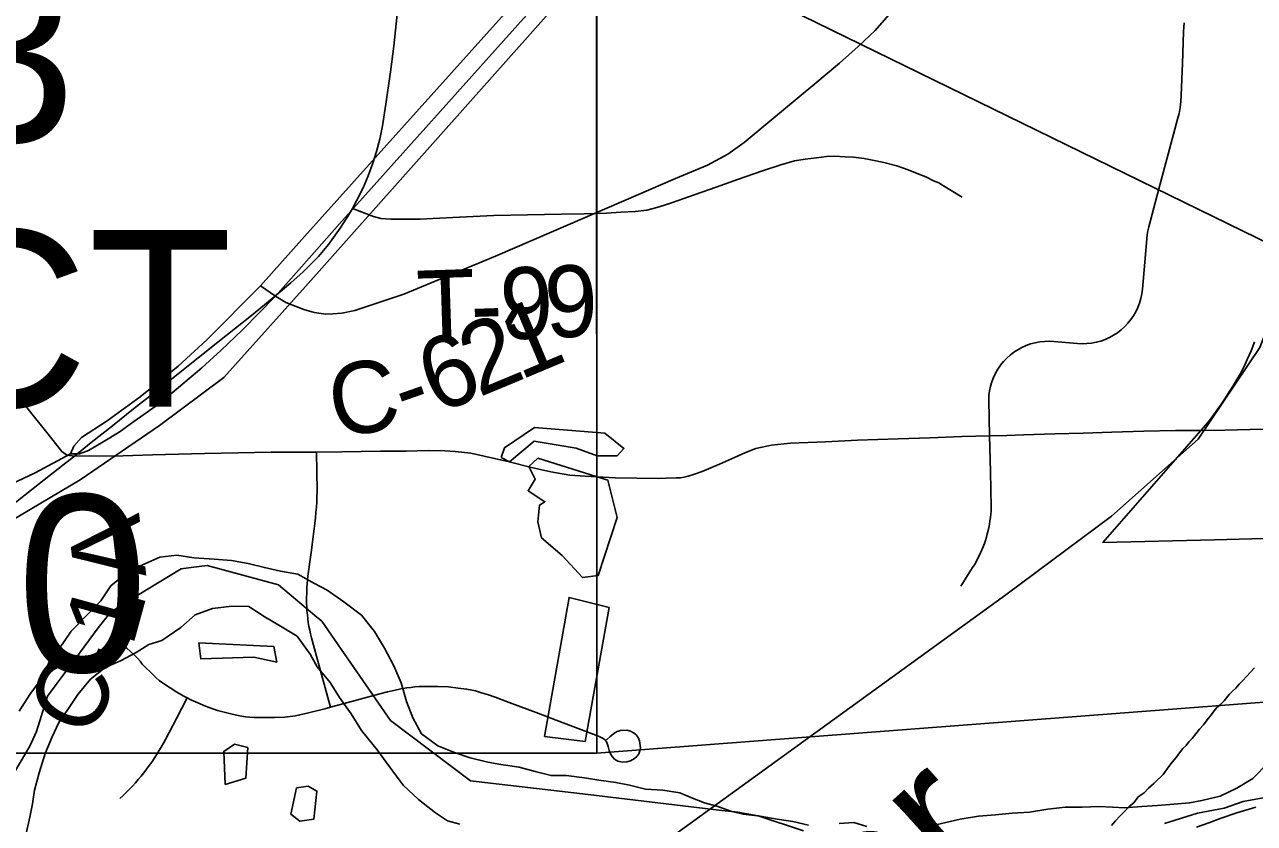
# Model space of a CAD drawing. Extents: x -6.1 to 38, y -7.7 to 22.
# Drawn here: x 4.995 to 5.97, y 18.594 to 19.227 of the extents above; entities that cross this region are included whole.
import ezdxf

# ---------------------------------------------------------------- set-up
doc = ezdxf.new("R2010")
doc.units = 0
for name, color, linetype in [('GM_X_Corporation', 7, 'Continuous'), ('GM_X_County_Road', 7, 'Continuous'), ('GM_X_County_Road_Text', 7, 'Continuous'), ('GM_X_Major_River', 7, 'Continuous'), ('GM_X_Major_River_Text', 7, 'Continuous'), ('GM_X_Minor_Lake', 7, 'Continuous'), ('GM_X_Minor_River', 7, 'Continuous'), ('GM_X_Rail_Line', 7, 'Continuous'), ('GM_X_Township_Road', 7, 'Continuous'), ('GM_X_Township_Road_Text', 7, 'Continuous'), ('GM_X_US_Route', 7, 'Continuous'), ('SH_Text', 7, 'Continuous')]:
    doc.layers.add(name, color=color, linetype=linetype)

msp = doc.modelspace()

# ---------------------------------------------------------------- linework, layer by layer
at = {"layer": 'GM_X_Corporation'}
for points in [[(5.9704, 18.97578), (5.96908, 18.97223), (5.9677, 18.9687), (5.96623, 18.9652), (5.96471, 18.96171), (5.96191, 18.95576), (5.95921, 18.9508), (5.95636, 18.94587), (5.95342, 18.941), (5.95044, 18.93618), (5.94735, 18.93141), (5.94418, 18.9267), (5.94091, 18.92204), (5.93469, 18.9136), (5.92962, 18.90779), (5.85031, 18.81673), (5.93858, 18.81896), (5.97794, 18.81995)], [(4.98437, 18.62941), (4.9995, 18.65526), (5.0049, 18.66688), (5.01365, 18.69493), (5.02803, 18.71436), (5.03887, 18.72902), (5.05368, 18.74904), (5.06379, 18.76178), (5.06483, 18.76241), (5.07927, 18.77124), (5.0921, 18.77908), (5.11964, 18.79595), (5.12546, 18.79667), (5.14011, 18.79852), (5.19671, 18.7833), (5.22703, 18.75764), (5.22783, 18.75696), (5.23099, 18.75429), (5.25639, 18.71764), (5.28554, 18.67556), (5.34884, 18.62786), (5.44222, 18.61682), (5.54829, 18.60429), (5.54852, 18.60426), (5.56082, 18.60302), (5.577, 18.60014), (5.61302, 18.58812)], [(5.89915, 18.59391), (5.92512, 18.60216), (5.94641, 18.60603), (5.96153, 18.61146), (5.98899, 18.6163)]]:
    msp.add_lwpolyline(points, dxfattribs=at)
at = {"layer": 'GM_X_County_Road'}
for points in [[(4.98326, 18.84453), (5.00739, 18.86365), (5.02582, 18.87809), (5.03494, 18.88525), (5.04812, 18.896), (5.06502, 18.90931), (5.08191, 18.92262), (5.09959, 18.9366), (5.11726, 18.95058), (5.13296, 18.96312), (5.14867, 18.97565), (5.16264, 18.98668), (5.17662, 18.99771), (5.19163, 19.01014), (5.20663, 19.02256), (5.21641, 19.03139), (5.22844, 19.04363), (5.23637, 19.05312), (5.24549, 19.06585), (5.25143, 19.07497), (5.25534, 19.08164), (5.25861, 19.08753), (5.26377, 19.09803), (5.26771, 19.10748), (5.27144, 19.11759), (5.27439, 19.12665), (5.277, 19.1365), (5.27917, 19.147), (5.28194, 19.16423), (5.28539, 19.18996), (5.28811, 19.21035), (5.2914, 19.24076)], [(5.18251, 19.02026), (5.19424, 19.01215), (5.20249, 19.00709), (5.21681, 19.00141), (5.22495, 18.99919), (5.23432, 18.99771), (5.23975, 18.99795), (5.24691, 18.99845), (5.25728, 19.00067), (5.29602, 19.01375), (5.36881, 19.04385), (5.47048, 19.08778), (5.51144, 19.1053), (5.53686, 19.11591), (5.5529, 19.12455), (5.56598, 19.13392), (5.58473, 19.14947), (5.62199, 19.18031), (5.64149, 19.19685), (5.65629, 19.20993), (5.66962, 19.22276), (5.68788, 19.24349)]]:
    msp.add_lwpolyline(points, dxfattribs=at)
at = {"layer": 'GM_X_Major_River'}
for points in [[(5.61689, 18.59268), (5.60439, 18.59564), (5.5919, 18.59745), (5.57865, 18.59964), (5.56502, 18.60144), (5.55518, 18.60365), (5.54418, 18.60775), (5.53433, 18.61034), (5.52485, 18.61407), (5.51499, 18.61817), (5.50136, 18.62036), (5.48774, 18.62103), (5.47486, 18.62435), (5.46425, 18.62656), (5.45063, 18.62836), (5.43927, 18.63018), (5.42489, 18.63199), (5.41279, 18.63191), (5.40028, 18.63524), (5.3874, 18.63856), (5.37302, 18.64074), (5.36279, 18.64257), (5.34878, 18.64589), (5.33627, 18.65036), (5.323, 18.65558), (5.31007, 18.66497), (5.30318, 18.67782), (5.29818, 18.69068), (5.29392, 18.70544), (5.28816, 18.71905), (5.28088, 18.73303), (5.27286, 18.74625), (5.26256, 18.75908), (5.2485, 18.7696), (5.2352, 18.77899), (5.22533, 18.78424), (5.21204, 18.79174), (5.19841, 18.79392), (5.18554, 18.79687), (5.17266, 18.8002), (5.1594, 18.80238), (5.14578, 18.80343), (5.12951, 18.80446), (5.11626, 18.80665), (5.10266, 18.80504), (5.08832, 18.79888), (5.07551, 18.79197), (5.06385, 18.78241), (5.05599, 18.7706), (5.03232, 18.74656), (5.0252, 18.73589), (5.01583, 18.72369), (5.00911, 18.70924), (4.99974, 18.69628), (4.99113, 18.68296)], [(4.99669, 18.58592), (4.99963, 18.59883), (5.00183, 18.60946), (5.00327, 18.62047), (5.00696, 18.63414), (5.01178, 18.64934), (5.01736, 18.66265), (5.02258, 18.67406), (5.0297, 18.68435), (5.03757, 18.69616), (5.0477, 18.70836), (5.05936, 18.71753), (5.07143, 18.72292), (5.08386, 18.72946), (5.09403, 18.73597), (5.10422, 18.73907), (5.11929, 18.74941), (5.13057, 18.75934), (5.14453, 18.76436), (5.15964, 18.76636), (5.17326, 18.76607), (5.18541, 18.75819), (5.19832, 18.75031), (5.21161, 18.74243), (5.22192, 18.7281), (5.22728, 18.71827), (5.23757, 18.70583), (5.24521, 18.69374)], [(5.85692, 18.59224), (5.86026, 18.5961), (5.86399, 18.59997), (5.86735, 18.60346), (5.87108, 18.60733), (5.87482, 18.61044), (5.87815, 18.61506), (5.88304, 18.61819), (5.88638, 18.62205), (5.8905, 18.62555), (5.89348, 18.62865), (5.8961, 18.63097), (5.89796, 18.63291), (5.90056, 18.63638), (5.90241, 18.63907), (5.90501, 18.64254), (5.90836, 18.6464), (5.91095, 18.64987), (5.91355, 18.65334), (5.91616, 18.65567), (5.91839, 18.65876), (5.921, 18.66146), (5.92397, 18.66494), (5.92694, 18.66879), (5.92992, 18.67227), (5.93289, 18.67613), (5.93623, 18.68037), (5.93994, 18.68538), (5.94368, 18.68849), (5.94629, 18.6912), (5.94815, 18.69352), (5.95038, 18.69622), (5.95299, 18.69893), (5.95561, 18.70126), (5.95821, 18.70434), (5.96119, 18.70744), (5.96417, 18.71054), (5.96715, 18.71401), (5.97051, 18.71749)], [(5.24521, 18.69374), (5.25437, 18.68091), (5.2624, 18.66769), (5.27499, 18.65223), (5.28491, 18.63864), (5.29559, 18.6243), (5.30777, 18.61301), (5.32108, 18.60248), (5.33057, 18.5961), (5.34042, 18.5935)], [(5.98116, 18.64212), (5.96914, 18.62952), (5.95633, 18.62185), (5.94313, 18.6157)], [(5.94313, 18.6157), (5.92878, 18.61219), (5.91896, 18.61023), (5.90649, 18.60939), (5.89364, 18.60817), (5.88116, 18.60733), (5.86755, 18.60648), (5.85772, 18.60679), (5.84712, 18.60748), (5.83389, 18.60702), (5.82027, 18.60692), (5.80667, 18.60532), (5.79193, 18.60294), (5.77832, 18.6021), (5.7651, 18.60087), (5.75149, 18.59964), (5.73713, 18.59727), (5.70994, 18.59103)], [(5.92438, 18.59093), (5.9342, 18.59441), (5.944, 18.59827), (5.95646, 18.60252), (5.97155, 18.60679)], [(5.66304, 18.59147), (5.65281, 18.59482), (5.64109, 18.59398)]]:
    msp.add_lwpolyline(points, dxfattribs=at)
at = {"layer": 'GM_X_Minor_Lake'}
for points in [[(5.46524, 18.88559), (5.47051, 18.8913), (5.45532, 18.90341), (5.39967, 18.90783), (5.37589, 18.89183), (5.37328, 18.88423)], [(5.37328, 18.88423), (5.37972, 18.88083), (5.39933, 18.8972), (5.43266, 18.89158), (5.44934, 18.88555), (5.46524, 18.88559)], [(5.40242, 18.88354), (5.39526, 18.87707), (5.40022, 18.86683), (5.39458, 18.85771), (5.40787, 18.84901), (5.40372, 18.84635), (5.40226, 18.83306), (5.40534, 18.82054), (5.42168, 18.80653)], [(5.42168, 18.80653), (5.43765, 18.78911), (5.45013, 18.79066), (5.46507, 18.83663), (5.45775, 18.86621), (5.40242, 18.88354)], [(5.45895, 18.76525), (5.42712, 18.77315), (5.40754, 18.66303)], [(5.40754, 18.66303), (5.43973, 18.65893), (5.45895, 18.76525)], [(5.13359, 18.73714), (5.13516, 18.72462), (5.17716, 18.72586), (5.19535, 18.72173)], [(5.19535, 18.72173), (5.19302, 18.73425), (5.13359, 18.73714)], [(5.17255, 18.65411), (5.16194, 18.65674), (5.15327, 18.65103), (5.15451, 18.62484)], [(5.15451, 18.62484), (5.17077, 18.62981), (5.17255, 18.65411)], [(5.21092, 18.62232), (5.20647, 18.60143), (5.21368, 18.59575), (5.22465, 18.5973)], [(5.22465, 18.5973), (5.2272, 18.6197), (5.22037, 18.62348), (5.21092, 18.62232)]]:
    msp.add_lwpolyline(points, dxfattribs=at)
at = {"layer": 'GM_X_Minor_River'}
msp.add_lwpolyline([(4.8608, 18.77196), (4.98429, 18.83357), (5.03941, 18.86634), (5.10243, 18.90938), (5.15337, 18.94745), (5.21821, 19.01967), (5.96039, 19.85374)], dxfattribs=at)
at = {"layer": 'GM_X_Rail_Line'}
msp.add_lwpolyline([(4.164, 17.08105), (4.22288, 17.11422), (4.28514, 17.16362), (4.3773, 17.2385), (4.46626, 17.31066), (4.52352, 17.37506), (4.57967, 17.45347), (4.643, 17.54537), (5.03778, 18.11028), (5.18813, 18.32179), (5.2285, 18.37664), (5.2671, 18.40903), (5.31379, 18.44323), (5.44065, 18.5342), (5.77322, 18.77518), (5.85708, 18.83753), (5.92575, 18.89871), (5.97472, 18.97128), (6.00159, 19.04095), (6.01392, 19.09362), (6.04108, 19.2873)], dxfattribs=at)
at = {"layer": 'GM_X_Township_Road'}
for points in [[(5.76043, 18.90123), (5.75969, 18.92961), (5.75988, 18.93332), (5.76036, 18.937), (5.76112, 18.94062), (5.76221, 18.94419), (5.76354, 18.94764), (5.7651, 18.951), (5.76695, 18.95421), (5.76909, 18.95728), (5.77141, 18.96015), (5.77397, 18.96285), (5.77672, 18.96533), (5.77966, 18.9676), (5.78274, 18.96962), (5.78601, 18.97141), (5.78942, 18.97292), (5.79288, 18.97416), (5.79648, 18.97513), (5.80013, 18.97582), (5.80383, 18.97622), (5.80752, 18.97633), (5.81122, 18.97615), (5.83012, 18.97448), (5.83382, 18.9743), (5.83756, 18.9744), (5.84126, 18.9748), (5.84491, 18.9755), (5.84851, 18.97647), (5.85201, 18.97772), (5.85538, 18.97925), (5.85865, 18.98104), (5.86178, 18.98307), (5.86471, 18.98535), (5.86747, 18.98785), (5.87003, 18.99056), (5.87235, 18.99346), (5.87443, 18.99652), (5.87628, 18.99976), (5.8779, 19.00312), (5.87922, 19.00659), (5.88027, 19.01017), (5.88103, 19.0138), (5.8815, 19.0175), (5.88341, 19.03908), (5.88532, 19.06067), (5.88584, 19.06394), (5.8866, 19.06716), (5.89466, 19.09716), (5.90207, 19.12472), (5.90948, 19.15227), (5.91062, 19.15697), (5.91148, 19.16174), (5.91204, 19.16653), (5.91238, 19.17136), (5.91327, 19.19646), (5.91416, 19.22155), (5.9144, 19.22527), (5.91473, 19.22867)], [(5.25534, 19.08164), (5.27194, 19.07512), (5.27787, 19.07376), (5.28583, 19.07304), (5.30904, 19.07317), (5.33486, 19.07447), (5.35113, 19.07525), (5.36739, 19.07604), (5.39419, 19.0765), (5.42099, 19.07695), (5.43891, 19.07747), (5.45685, 19.078), (5.46799, 19.07858), (5.47953, 19.07917), (5.4886, 19.08028), (5.49675, 19.08243), (5.50281, 19.08419), (5.50907, 19.0864), (5.527, 19.0926), (5.54378, 19.09861), (5.56055, 19.10461), (5.58049, 19.11136), (5.595, 19.11627), (5.60583, 19.1194), (5.61417, 19.12063), (5.62311, 19.12181), (5.63119, 19.12272), (5.63719, 19.12304), (5.64592, 19.12266), (5.65244, 19.1224), (5.66105, 19.12109), (5.6675, 19.11985), (5.6767, 19.11796), (5.68687, 19.11542), (5.69587, 19.11229), (5.70159, 19.10996), (5.70995, 19.10655), (5.71608, 19.10349), (5.72006, 19.10179), (5.72391, 19.09964), (5.7387, 19.09052)], [(4.98192, 18.94321), (5.00121, 18.91886), (5.01309, 18.90386), (5.02497, 18.88886), (5.02698, 18.8873), (5.02924, 18.88608), (5.03494, 18.88525)], [(5.9285, 18.90563), (5.94702, 18.90579), (5.96702, 18.90621), (5.98887, 18.9068), (6.0173, 18.90799), (6.03468, 18.90872), (6.05205, 18.90944), (6.06798, 18.90975), (6.08392, 18.91005), (6.10601, 18.91047), (6.12744, 18.91113), (6.15004, 18.91213), (6.16462, 18.91288), (6.18297, 18.91321), (6.20106, 18.91297), (6.22299, 18.91288), (6.24683, 18.91347), (6.26381, 18.91403), (6.28079, 18.91459), (6.31087, 18.91555), (6.33696, 18.91672), (6.35463, 18.91734), (6.37229, 18.91797)], [(5.03494, 18.88525), (5.04728, 18.88555), (5.06574, 18.88529), (5.08127, 18.88579), (5.09679, 18.88629), (5.11736, 18.88677), (5.13794, 18.88725), (5.16447, 18.88776), (5.19101, 18.88827), (5.20893, 18.88835), (5.22687, 18.88843), (5.24693, 18.88871), (5.27758, 18.88914), (5.29781, 18.88922), (5.31542, 18.88961), (5.32845, 18.88945), (5.33667, 18.88898), (5.34923, 18.88748), (5.37854, 18.88108), (5.39726, 18.87626), (5.41274, 18.87279), (5.42767, 18.87018), (5.43992, 18.86931), (5.46361, 18.86813), (5.48084, 18.86784), (5.49807, 18.86755), (5.50413, 18.86767), (5.51204, 18.86797), (5.51536, 18.86813), (5.51828, 18.8686), (5.52151, 18.86939), (5.5265, 18.87084), (5.53257, 18.8731), (5.54624, 18.87878), (5.55572, 18.88313), (5.56646, 18.88779), (5.57523, 18.89135), (5.58755, 18.8938), (5.60264, 18.89546), (5.63037, 18.89648), (5.65572, 18.89775), (5.6718, 18.8983), (5.68788, 18.89885), (5.71329, 18.89976), (5.73871, 18.90067), (5.76043, 18.90123), (5.77399, 18.90168), (5.78759, 18.90224), (5.81205, 18.90281), (5.83471, 18.90353), (5.85739, 18.90425), (5.88265, 18.90494), (5.90791, 18.90563), (5.9285, 18.90563)], [(5.73773, 18.78219), (5.74698, 18.79679), (5.74835, 18.79907), (5.74968, 18.80137), (5.75096, 18.80371), (5.75214, 18.80609), (5.75328, 18.80851), (5.75433, 18.81094), (5.75532, 18.81342), (5.75627, 18.81591), (5.75712, 18.81843), (5.75788, 18.82098), (5.7586, 18.82354), (5.75926, 18.82613), (5.75978, 18.82873), (5.76031, 18.83135), (5.76073, 18.83398), (5.76106, 18.83662), (5.76131, 18.83926), (5.76154, 18.84192), (5.76164, 18.84458), (5.76104, 18.87291), (5.76043, 18.90123)], [(5.23796, 18.68608), (5.23077, 18.71215), (5.22357, 18.73823), (5.22277, 18.74121), (5.22206, 18.7442), (5.22145, 18.74721), (5.22088, 18.75023), (5.22036, 18.75327), (5.21994, 18.75631), (5.21961, 18.75937), (5.21932, 18.76243), (5.21909, 18.7655), (5.21895, 18.76857), (5.21914, 18.78087), (5.21933, 18.78393), (5.21966, 18.787), (5.22, 18.79006), (5.2225, 18.80884), (5.225, 18.82763), (5.22552, 18.8319), (5.22599, 18.83618), (5.22642, 18.84046), (5.22675, 18.84475), (5.227, 18.84905), (5.22718, 18.85334), (5.22733, 18.85764), (5.22687, 18.88843)], [(5.063, 18.73926), (5.0697, 18.73682), (5.07649, 18.73294), (5.07951, 18.73035), (5.08484, 18.72498), (5.08697, 18.72266), (5.08875, 18.72032), (5.09146, 18.7174), (5.09509, 18.7142), (5.09744, 18.7117), (5.09986, 18.70935), (5.10221, 18.70729), (5.10477, 18.70537), (5.11096, 18.70138), (5.11616, 18.69797), (5.12114, 18.69512), (5.12436, 18.69351), (5.12712, 18.69206), (5.13282, 18.6895), (5.13879, 18.68708), (5.14456, 18.68494), (5.14847, 18.68366), (5.15353, 18.68224), (5.16001, 18.68053), (5.16605, 18.67939), (5.17068, 18.67847), (5.17737, 18.67804), (5.18377, 18.67796), (5.1936, 18.67789), (5.20179, 18.67818), (5.21018, 18.67939), (5.2205, 18.68167), (5.23339, 18.6848), (5.23796, 18.68608), (5.25161, 18.68985), (5.27702, 18.69675), (5.28321, 18.69832), (5.28805, 18.69939), (5.29368, 18.7006), (5.29844, 18.70159), (5.3015, 18.70188), (5.30485, 18.70238), (5.30834, 18.70259), (5.32314, 18.70266), (5.3314, 18.70224), (5.33902, 18.70131), (5.34578, 18.70046), (5.35276, 18.69903), (5.35773, 18.69747), (5.36321, 18.6959), (5.36856, 18.69413), (5.38175, 18.68896), (5.40094, 18.68184), (5.42247, 18.67375), (5.444, 18.66565), (5.45027, 18.66313), (5.45357, 18.66173), (5.45569, 18.66022), (5.45713, 18.65825), (5.45803, 18.65508), (5.4588, 18.65177), (5.45985, 18.64926), (5.46123, 18.647), (5.46308, 18.64494), (5.46585, 18.64337), (5.46937, 18.64261), (5.47297, 18.64281), (5.47589, 18.64373), (5.47904, 18.64541), (5.48108, 18.64737), (5.48224, 18.64922), (5.48313, 18.65153), (5.48365, 18.65391), (5.48301, 18.65946), (5.48194, 18.66209), (5.4803, 18.66423), (5.47874, 18.66558), (5.47582, 18.66715), (5.47283, 18.66786), (5.46792, 18.66772), (5.46529, 18.66686), (5.46322, 18.6658), (5.45952, 18.66302), (5.45669, 18.66028)], [(5.07099, 18.61373), (5.07355, 18.61611), (5.07606, 18.61855), (5.07853, 18.62105), (5.08094, 18.62358), (5.08327, 18.62617), (5.08559, 18.6288), (5.08787, 18.63148), (5.09005, 18.63423), (5.09218, 18.637), (5.09427, 18.63981), (5.0963, 18.64266), (5.09825, 18.64557), (5.10014, 18.6485), (5.102, 18.65149), (5.1038, 18.65449), (5.1055, 18.65755), (5.10717, 18.66064), (5.11576, 18.67707), (5.12436, 18.69351)]]:
    msp.add_lwpolyline(points, dxfattribs=at)
at = {"layer": 'GM_X_US_Route'}
for points in [[(5.03183, 18.88699), (5.03441, 18.89324), (5.0406, 18.89993), (5.0609, 18.9132), (5.08696, 18.93231), (5.11714, 18.95663), (5.13994, 18.97748), (5.18251, 19.02026), (5.21725, 19.05934), (5.24548, 19.09062), (5.38511, 19.2461), (5.46459, 19.33557), (5.54102, 19.42069), (5.69977, 19.59745), (5.78771, 19.69583), (5.87696, 19.79507)], [(5.22096, 19.04223), (5.245, 19.06931), (5.39336, 19.23481), (5.54633, 19.40534), (5.68905, 19.56449), (5.83324, 19.72538), (5.88289, 19.78076)], [(5.03183, 18.88699), (5.03885, 18.88699), (5.04608, 18.88962), (5.05786, 18.89648), (5.07045, 18.9043), (5.08215, 18.91277), (5.10237, 18.92688), (5.13603, 18.95512), (5.15101, 18.96901), (5.16817, 18.9853), (5.19424, 19.01215), (5.22096, 19.04223)], [(4.98037, 18.86078), (5.00397, 18.87186), (5.03183, 18.88699)]]:
    msp.add_lwpolyline(points, dxfattribs=at)
at = {"layer": 'SH_Text'}
for points in [[(3.61627, 19.3143), (5.44915, 19.3143), (5.44915, 18.64981), (3.61627, 18.64981)], [(5.44879, 19.3143), (6.62446, 18.73967), (5.44915, 18.64981)]]:
    msp.add_lwpolyline(points, close=True, dxfattribs=at)

# ---------------------------------------------------------------- texts
at = {"layer": 'GM_X_County_Road_Text'}
for s, rotation, p in [('1', 22.83649, (5.38803, 18.94519)), ('2', 22.59139, (5.35546, 18.93165)), ('6', 21.60993, (5.32194, 18.91835)), ('C', 9.99554, (5.24188, 18.89912)), ('-', 19.29466, (5.29757, 18.90976)), ('A', 96.63724, (5.09197, 18.79029)), ('1', 74.68144, (5.08101, 18.73324)), ('-', 64.90792, (5.06755, 18.70238)), ('C', 63.31266, (5.046, 18.65944))]:
    msp.add_text(s, height=0.05682, rotation=rotation, dxfattribs=at).set_placement(p)
at = {"layer": 'GM_X_Major_River_Text'}
msp.add_text('River', height=0.113721, rotation=42.01408, dxfattribs=at).set_placement((5.50826, 18.33699))
at = {"layer": 'GM_X_Township_Road_Text'}
for s, rotation, p in [('T', 1.86032, (5.30722, 18.97539)), ('9', 1.99064, (5.37316, 18.97755)), ('9', 2.56593, (5.40876, 18.97879)), ('-', 1.88635, (5.34973, 18.97677))]:
    msp.add_text(s, height=0.05682, rotation=rotation, dxfattribs=at).set_placement(p)
at = {"layer": 'SH_Text'}
for s, p in [('GEA-44-14.93', (3.83924, 19.1344)), ('END PROJECT', (3.83924, 18.9244)), ('STA. 16+75.00', (3.83924, 18.7144))]:
    msp.add_text(s, height=0.1399997, dxfattribs=at).set_placement(p)

doc.saveas('drawing.dxf')
